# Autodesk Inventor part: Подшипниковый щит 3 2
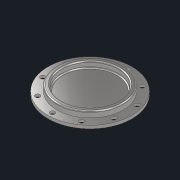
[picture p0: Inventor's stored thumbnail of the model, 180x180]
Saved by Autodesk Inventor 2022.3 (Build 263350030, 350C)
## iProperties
Created: 2022-08
Part Number: Подшипниковый щит 3 2
Material: Сталь 40ХНМА
Document SubType Name: Modeling
Designer: Карташов
Density: 7.85 g/cm^3
Appearance: С умеренной полировкой
Author: Карташов
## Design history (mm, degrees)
sketch "Эскиз1"
  geometry: L1 (0, 0)-(0, 34.001); L2 (45, -5)-(70, -5); L3 (70, -5)-(70, 0); L4 (70, 0)-(55, 0); L5 (55, 0)-(55, 8); L6 (53, 10)-(49, 10); L7 (47, 8)-(47, 2); L8 (45, 0)-(0, 0); L9 (45, -5)-(43, -7); L10 (43, -7)-(0, -7); L11 (0, -7)-(0, 0); A1 r 2 centre (45, 2) between (45, 0) and (47, 2); A2 r 2 centre (53, 8) between (55, 8) and (53, 10); A3 r 2 centre (49, 8) between (49, 10) and (47, 8); 4 further points
  constraints: 22 end point, 6 point on circle, 6 tangent, 5 horizontal, 4 point on line, 3 centre point, 3 vertical, 2 midpoint, 2 perpendicular
  dimensions: "d0" = 110 diameter of L5 point (0, 17); "d1" = 140 diameter of L3 L1; "d4" = 5 distance of L2.end L3.end; "d5" = 10 distance between parallel lines of L8 L6; "d6" = 8 distance of point (55, 10) point (47, 10); "d7" = 2 radius of A1; "d21" = 2 horizontal distance of L2.start L9.end; "d22" = 2 horizontal distance of L2.start L9.end; "d23" = 90 diameter of L2.start L1; "d24" = 2 radius of A2; "d25" = 2 radius of A3 (derived); "d26" = 17 distance from line of point (51, 10) L10
revolve "Вращение1" sketch "Эскиз1" stored, may be unused: angle "d9" = 90 deg
sketch "Эскиз2"
  geometry: C1 r 55 at (0, 0) reference; C2 r 70 at (0, 0) reference; 2 further points
  constraints: 1 vertical alignment
  dimensions: "d10" = 62.5 distance of point (0, 0) point (0, -62.5)
  node "Спроецированная петля1"
sketch "Эскиз3"
  geometry: 2 further points
hole "Отверстие1" sketch "Эскиз3" at (0, 62.5) diameter "d11" = 8; stored, may be unused: countersink angle "d15" = 90 deg, drill point angle "d17" = 0 deg; dims "d12" = 6, "d13" = 13, "d14" = 1, "d16" = 22.5
pattern_circular "Круговой массив1" dims angle "d19" = 360 deg
node "Твердое тело1"
